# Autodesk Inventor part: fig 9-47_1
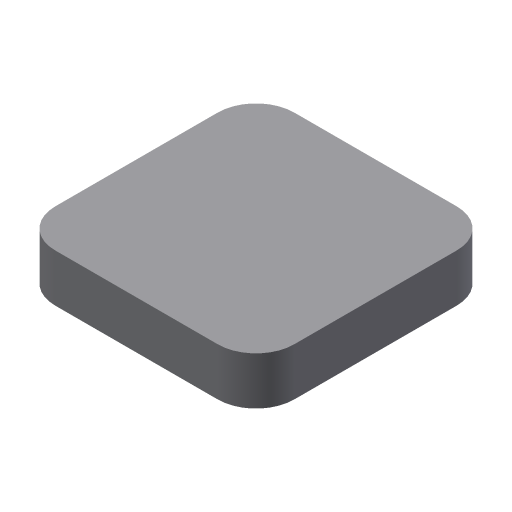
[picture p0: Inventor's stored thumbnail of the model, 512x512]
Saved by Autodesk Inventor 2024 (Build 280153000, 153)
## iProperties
Created: 2013-03
Part Number: fig 9-47_1
Material: Generic
Document SubType Name: Modeling
Designer: CADCIM
Density: 1 g/cm^3
Appearance: Default
Author: CADCIM
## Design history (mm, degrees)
sketch "Sketch1"
  geometry: L1 (-12.5, 12.5)-(12.5, 12.5); L2 (12.5, 12.5)-(12.5, -12.5); L3 (12.5, -12.5)-(-12.5, -12.5); L4 (-12.5, -12.5)-(-12.5, 12.5); 1 further point
  constraints: 8 end point, 2 parallel, 1 horizontal, 1 perpendicular
  dimensions: "d0" = 25 distance of L1.start L1.end; "d2" = 25 distance of L1.end L2.end
extrude "Extrusion1" new body sketch "Sketch1" distance "d3" = 5; taper "d4" = 0 deg
fillet "Fillet1" dims "d5" = 4
body "Solid1"
